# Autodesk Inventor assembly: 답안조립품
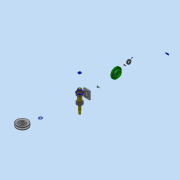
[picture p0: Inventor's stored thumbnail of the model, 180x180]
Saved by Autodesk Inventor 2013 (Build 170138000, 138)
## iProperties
Created: 2017-05
Part Number: 답안조립품
Document SubType Name: Assembly
Designer: Administrator
Author: Administrator
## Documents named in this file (20)
- C:\Users\Administrator\Desktop\470508V1024\답안조립품.iam
- C:\Users\Administrator\Desktop\470508V1024\V-벨트풀리.ipt
- C:\Users\Administrator\Desktop\470508V1024\너트 M10.ipt
- C:\Users\Administrator\Desktop\470508V1024\멈춤링 15 x 1.ipt
- C:\Users\Administrator\Desktop\470508V1024\멈춤링 35x1.6.ipt
- C:\Users\Administrator\Desktop\470508V1024\베어링 15 x 35 x 11.ipt
- C:\Users\Administrator\Desktop\470508V1024\본체.ipt
- C:\Users\Administrator\Desktop\470508V1024\볼트 M4 x 10.ipt
- C:\Users\Administrator\Desktop\470508V1024\부시1.ipt
- C:\Users\Administrator\Desktop\470508V1024\부시2.ipt
- C:\Users\Administrator\Desktop\470508V1024\사이드 커버.ipt
- 사이드 커버.ipt
- C:\Users\Administrator\Desktop\470508V1024\십자볼트 M3 x 10.ipt
- C:\Users\Administrator\Desktop\470508V1024\오일 실 15 25 7.ipt
- C:\Users\Administrator\Desktop\470508V1024\와셔 3x6.ipt
- C:\Users\Administrator\Desktop\470508V1024\와셔 4x16.ipt
- C:\Users\Administrator\Desktop\470508V1024\와셔 10x21.ipt
- C:\Users\Administrator\Desktop\470508V1024\축.ipt
- C:\Users\Administrator\Desktop\470508V1024\키 4 x 4 x 18.ipt
- C:\Users\Administrator\Desktop\470508V1024\탑 커버.ipt
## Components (2 placed, 2 different names)
1. V-벨트풀리:1
2. ISO 4017 M4 x 10:1
